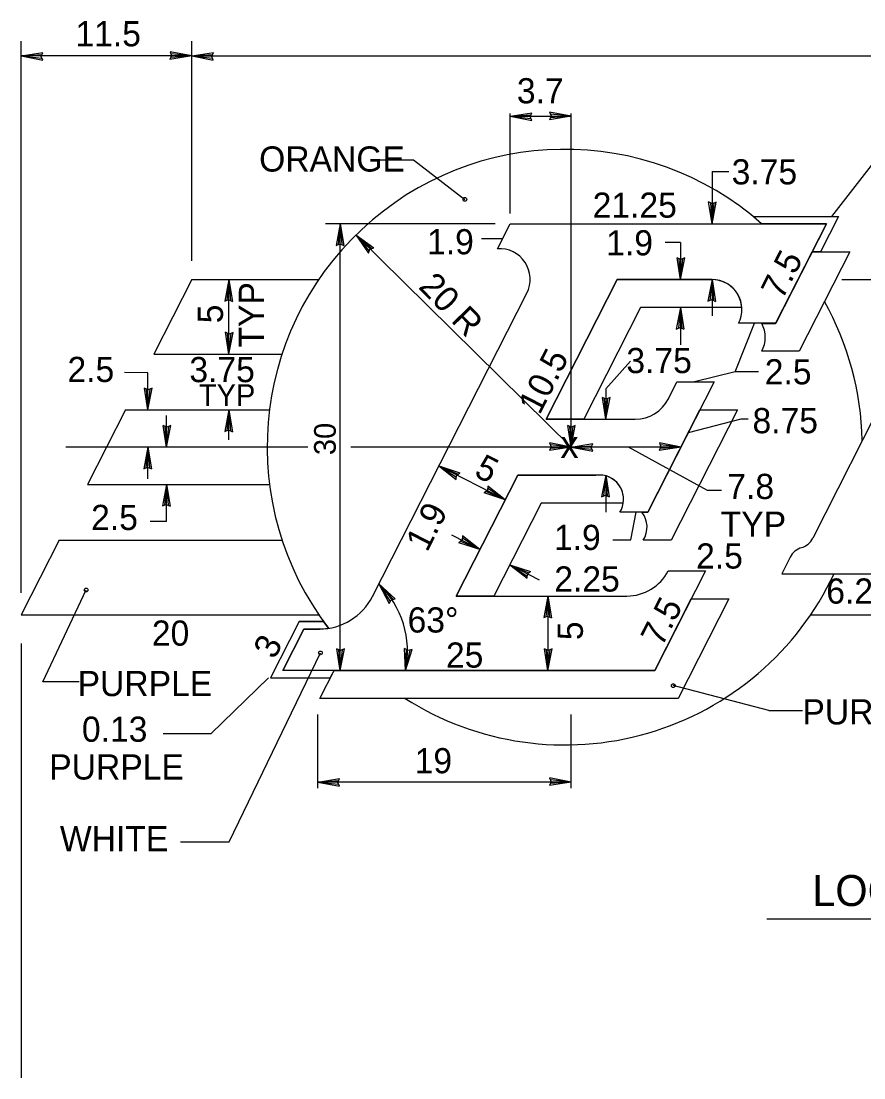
# Model space of a CAD drawing. Extents: x 10268197 to 10268739, y 2141503 to 2142677.
# Drawn here: x 10268676.64 to 10268700.09, y 2142394.92 to 2142424.3 of the extents above; entities that cross this region are included whole.
import ezdxf

# ---------------------------------------------------------------- set-up
doc = ezdxf.new("R2010")
doc.units = 0
for name, color, linetype in [('1', 7, 'Continuous'), ('21', 7, 'Continuous'), ('Default', 7, 'Continuous')]:
    doc.layers.add(name, color=color, linetype=linetype)

msp = doc.modelspace()

# ---------------------------------------------------------------- linework, layer by layer
at = {"layer": '1'}
for p, q in [((10268676.642, 2142408.409), (10268676.642, 2142423.746)), ((10268681.389, 2142417.633), (10268681.389, 2142423.746)), ((10268681.389, 2142423.333), (10268676.642, 2142423.333)), ((10268681.389, 2142423.333), (10268681.994, 2142423.429)), ((10268681.389, 2142423.333), (10268681.968, 2142423.373)), ((10268681.389, 2142423.333), (10268706.542, 2142423.333)), ((10268681.389, 2142423.333), (10268681.99, 2142423.216)), ((10268681.389, 2142423.333), (10268681.967, 2142423.272)), ((10268681.946, 2142423.323), (10268681.994, 2142423.429)), ((10268681.99, 2142423.216), (10268681.946, 2142423.323)), ((10268690.249, 2142421.657), (10268690.855, 2142421.753)), ((10268690.249, 2142418.952), (10268690.249, 2142421.73)), ((10268690.807, 2142421.647), (10268690.855, 2142421.753)), ((10268691.947, 2142412.457), (10268691.947, 2142421.73)), ((10268690.249, 2142421.657), (10268690.829, 2142421.698)), ((10268690.249, 2142421.657), (10268691.947, 2142421.657)), ((10268690.249, 2142421.657), (10268690.851, 2142421.541)), ((10268690.249, 2142421.657), (10268690.828, 2142421.597)), ((10268690.851, 2142421.541), (10268690.807, 2142421.647)), ((10268699.201, 2142418.868), (10268701.226, 2142421.486)), ((10268686.626, 2142420.448), (10268687.563, 2142420.448)), ((10268687.563, 2142420.448), (10268688.991, 2142419.346)), ((10268695.869, 2142420.118), (10268695.869, 2142418.667)), ((10268695.869, 2142420.118), (10268696.338, 2142420.118)), ((10268695.869, 2142418.667), (10268695.773, 2142419.273)), ((10268695.879, 2142419.224), (10268695.773, 2142419.273)), ((10268695.869, 2142418.667), (10268695.829, 2142419.247)), ((10268695.869, 2142418.667), (10268695.986, 2142419.269)), ((10268695.869, 2142418.667), (10268695.93, 2142419.246)), ((10268695.986, 2142419.269), (10268695.879, 2142419.224)), ((10268689.835, 2142418.667), (10268685.11, 2142418.667)), ((10268685.524, 2142418.667), (10268685.407, 2142418.066)), ((10268685.524, 2142418.667), (10268685.463, 2142418.089)), ((10268685.524, 2142406.246), (10268685.524, 2142418.667)), ((10268685.524, 2142418.667), (10268685.619, 2142418.062)), ((10268685.524, 2142418.667), (10268685.564, 2142418.088)), ((10268691.947, 2142412.457), (10268685.959, 2142418.356)), ((10268685.959, 2142418.356), (10268686.457, 2142418)), ((10268685.959, 2142418.356), (10268686.305, 2142417.851)), ((10268685.959, 2142418.356), (10268686.329, 2142417.907)), ((10268685.959, 2142418.356), (10268686.401, 2142417.979)), ((10268690.038, 2142418.253), (10268689.449, 2142418.253)), ((10268685.407, 2142418.066), (10268685.514, 2142418.11)), ((10268685.514, 2142418.11), (10268685.619, 2142418.062)), ((10268686.305, 2142417.851), (10268686.349, 2142417.959)), ((10268686.349, 2142417.959), (10268686.457, 2142418)), ((10268694.99, 2142418.149), (10268694.56, 2142418.149)), ((10268694.99, 2142418.149), (10268694.99, 2142417.115)), ((10268694.99, 2142417.115), (10268694.894, 2142417.72)), ((10268694.999, 2142417.672), (10268694.894, 2142417.72)), ((10268694.99, 2142417.115), (10268694.95, 2142417.695)), ((10268694.99, 2142417.115), (10268695.107, 2142417.716)), ((10268694.99, 2142417.115), (10268695.051, 2142417.693)), ((10268695.107, 2142417.716), (10268694.999, 2142417.672)), ((10268697.636, 2142415.898), (10268698.652, 2142417.891)), ((10268699.698, 2142417.891), (10268698.287, 2142415.124)), ((10268698.652, 2142417.891), (10268699.698, 2142417.891)), ((10268682.424, 2142417.115), (10268682.307, 2142416.513)), ((10268682.424, 2142417.115), (10268682.363, 2142416.536)), ((10268682.424, 2142415.044), (10268682.424, 2142417.115)), ((10268682.424, 2142417.115), (10268682.52, 2142416.509)), ((10268682.424, 2142417.115), (10268682.464, 2142416.535)), ((10268691.253, 2142413.233), (10268693.231, 2142417.115)), ((10268693.231, 2142417.115), (10268695.869, 2142417.115)), ((10268695.869, 2142417.115), (10268695.752, 2142416.513)), ((10268695.869, 2142417.115), (10268695.808, 2142416.536)), ((10268695.869, 2142417.115), (10268695.965, 2142416.509)), ((10268695.869, 2142417.115), (10268695.91, 2142416.535)), ((10268695.869, 2142417.115), (10268695.869, 2142416.104)), ((10268682.307, 2142416.513), (10268682.414, 2142416.557)), ((10268682.414, 2142416.557), (10268682.52, 2142416.509)), ((10268695.752, 2142416.513), (10268695.859, 2142416.557)), ((10268695.859, 2142416.557), (10268695.965, 2142416.509)), ((10268693.881, 2142416.339), (10268692.299, 2142413.233)), ((10268696.696, 2142416.339), (10268693.881, 2142416.339)), ((10268694.99, 2142416.339), (10268694.873, 2142415.737)), ((10268694.99, 2142416.339), (10268694.93, 2142415.76)), ((10268694.99, 2142416.339), (10268694.99, 2142415.304)), ((10268694.99, 2142416.339), (10268695.086, 2142415.733)), ((10268694.99, 2142416.339), (10268695.031, 2142415.759)), ((10268696.515, 2142414.546), (10268697.046, 2142415.9)), ((10268697.251, 2142415.898), (10268697.636, 2142415.898)), ((10268682.424, 2142415.044), (10268682.328, 2142415.65)), ((10268682.433, 2142415.602), (10268682.328, 2142415.65)), ((10268682.424, 2142415.044), (10268682.382, 2142415.624)), ((10268682.424, 2142415.044), (10268682.541, 2142415.646)), ((10268682.424, 2142415.044), (10268682.484, 2142415.623)), ((10268682.541, 2142415.646), (10268682.433, 2142415.602)), ((10268694.873, 2142415.737), (10268694.981, 2142415.781)), ((10268694.981, 2142415.781), (10268695.086, 2142415.733)), ((10268698.287, 2142415.124), (10268697.252, 2142415.124)), ((10268693.594, 2142414.845), (10268692.912, 2142414.075)), ((10268680.172, 2142414.527), (10268679.516, 2142414.531)), ((10268680.172, 2142413.492), (10268680.172, 2142414.527)), ((10268696.515, 2142414.546), (10268695.375, 2142414.268)), ((10268697.157, 2142414.546), (10268696.515, 2142414.546)), ((10268680.172, 2142413.492), (10268680.076, 2142414.097)), ((10268680.181, 2142414.049), (10268680.076, 2142414.097)), ((10268680.172, 2142413.492), (10268680.288, 2142414.093)), ((10268680.288, 2142414.093), (10268680.181, 2142414.049)), ((10268680.172, 2142413.492), (10268680.131, 2142414.072)), ((10268680.172, 2142413.492), (10268680.232, 2142414.07)), ((10268692.912, 2142413.233), (10268692.816, 2142413.838)), ((10268692.921, 2142413.79), (10268692.816, 2142413.838)), ((10268692.912, 2142413.233), (10268692.871, 2142413.813)), ((10268692.912, 2142414.075), (10268692.912, 2142413.233)), ((10268692.912, 2142413.233), (10268693.028, 2142413.835)), ((10268692.912, 2142413.233), (10268692.972, 2142413.811)), ((10268693.028, 2142413.835), (10268692.921, 2142413.79)), ((10268680.69, 2142412.457), (10268680.69, 2142413.336)), ((10268682.424, 2142413.492), (10268682.307, 2142412.89)), ((10268682.424, 2142413.492), (10268682.363, 2142412.914)), ((10268682.424, 2142412.664), (10268682.424, 2142413.492)), ((10268682.424, 2142413.492), (10268682.52, 2142412.886)), ((10268682.424, 2142413.492), (10268682.464, 2142412.912)), ((10268692.299, 2142413.233), (10268691.253, 2142413.233)), ((10268694.08, 2142410.645), (10268695.531, 2142413.492)), ((10268696.576, 2142413.492), (10268694.73, 2142409.869)), ((10268696.669, 2142413.234), (10268695.206, 2142412.854)), ((10268695.531, 2142413.492), (10268696.576, 2142413.492)), ((10268696.875, 2142413.234), (10268696.669, 2142413.234)), ((10268680.69, 2142412.457), (10268680.593, 2142413.062)), ((10268680.699, 2142413.014), (10268680.593, 2142413.062)), ((10268680.69, 2142412.457), (10268680.649, 2142413.036)), ((10268680.69, 2142412.457), (10268680.806, 2142413.058)), ((10268680.69, 2142412.457), (10268680.75, 2142413.035)), ((10268680.806, 2142413.058), (10268680.699, 2142413.014)), ((10268682.307, 2142412.89), (10268682.414, 2142412.935)), ((10268682.414, 2142412.935), (10268682.52, 2142412.886)), ((10268691.947, 2142412.457), (10268691.851, 2142413.062)), ((10268691.956, 2142413.014), (10268691.851, 2142413.062)), ((10268691.947, 2142412.457), (10268691.906, 2142413.036)), ((10268691.947, 2142412.457), (10268692.063, 2142413.058)), ((10268691.947, 2142412.457), (10268692.007, 2142413.035)), ((10268692.063, 2142413.058), (10268691.956, 2142413.014)), ((10268684.62, 2142412.457), (10268677.886, 2142412.457)), ((10268680.172, 2142412.457), (10268680.055, 2142411.855)), ((10268680.172, 2142412.457), (10268680.111, 2142411.878)), ((10268680.172, 2142411.577), (10268680.172, 2142412.457)), ((10268680.172, 2142412.457), (10268680.268, 2142411.851)), ((10268680.172, 2142412.457), (10268680.213, 2142411.877)), ((10268691.947, 2142412.457), (10268685.814, 2142412.457)), ((10268691.389, 2142412.467), (10268691.341, 2142412.361)), ((10268691.947, 2142412.457), (10268691.341, 2142412.361)), ((10268691.947, 2142412.457), (10268691.345, 2142412.574)), ((10268691.345, 2142412.574), (10268691.389, 2142412.467)), ((10268691.947, 2142412.457), (10268691.367, 2142412.416)), ((10268691.947, 2142412.457), (10268691.369, 2142412.517)), ((10268691.947, 2142412.457), (10268692.552, 2142412.553)), ((10268691.947, 2142412.457), (10268692.526, 2142412.497)), ((10268695.004, 2142412.457), (10268691.947, 2142412.457)), ((10268691.947, 2142412.457), (10268692.548, 2142412.34)), ((10268691.947, 2142412.457), (10268692.525, 2142412.396)), ((10268692.504, 2142412.447), (10268692.552, 2142412.553)), ((10268692.548, 2142412.34), (10268692.504, 2142412.447)), ((10268695.743, 2142411.252), (10268693.54, 2142412.457)), ((10268694.446, 2142412.467), (10268694.398, 2142412.361)), ((10268695.004, 2142412.457), (10268694.398, 2142412.361)), ((10268695.004, 2142412.457), (10268694.402, 2142412.574)), ((10268694.402, 2142412.574), (10268694.446, 2142412.467)), ((10268695.004, 2142412.457), (10268694.424, 2142412.416)), ((10268695.004, 2142412.457), (10268694.425, 2142412.517)), ((10268680.055, 2142411.855), (10268680.162, 2142411.9)), ((10268680.162, 2142411.9), (10268680.268, 2142411.851)), ((10268690.113, 2142410.993), (10268688.267, 2142411.933)), ((10268688.267, 2142411.933), (10268688.85, 2142411.744)), ((10268688.267, 2142411.933), (10268688.751, 2142411.556)), ((10268688.267, 2142411.933), (10268688.755, 2142411.617)), ((10268688.267, 2142411.933), (10268688.802, 2142411.706)), ((10268688.76, 2142411.671), (10268688.85, 2142411.744)), ((10268688.749, 2142408.317), (10268690.463, 2142411.68)), ((10268688.751, 2142411.556), (10268688.76, 2142411.671)), ((10268690.463, 2142411.68), (10268692.636, 2142411.673)), ((10268692.912, 2142411.68), (10268692.795, 2142411.079)), ((10268692.912, 2142411.68), (10268692.851, 2142411.102)), ((10268692.912, 2142411.68), (10268693.008, 2142411.075)), ((10268692.912, 2142411.68), (10268692.952, 2142411.101)), ((10268692.912, 2142411.68), (10268692.912, 2142410.645)), ((10268680.69, 2142411.422), (10268680.573, 2142410.82)), ((10268680.69, 2142411.422), (10268680.629, 2142410.843)), ((10268680.69, 2142410.387), (10268680.69, 2142411.422)), ((10268680.69, 2142411.422), (10268680.786, 2142410.816)), ((10268680.69, 2142411.422), (10268680.73, 2142410.842)), ((10268689.62, 2142411.254), (10268689.529, 2142411.182)), ((10268690.113, 2142410.993), (10268689.529, 2142411.182)), ((10268690.113, 2142410.993), (10268689.577, 2142411.219)), ((10268689.629, 2142411.37), (10268689.62, 2142411.254)), ((10268690.113, 2142410.993), (10268689.625, 2142411.309)), ((10268690.113, 2142410.993), (10268689.629, 2142411.37)), ((10268696.129, 2142411.252), (10268695.743, 2142411.252)), ((10268680.573, 2142410.82), (10268680.68, 2142410.865)), ((10268680.68, 2142410.865), (10268680.786, 2142410.816)), ((10268691.112, 2142410.903), (10268689.794, 2142408.317)), ((10268693.397, 2142410.895), (10268691.112, 2142410.903)), ((10268692.795, 2142411.079), (10268692.902, 2142411.123)), ((10268692.902, 2142411.123), (10268693.008, 2142411.075)), ((10268693.603, 2142409.882), (10268693.759, 2142410.645)), ((10268693.918, 2142410.645), (10268694.08, 2142410.645)), ((10268680.69, 2142410.387), (10268680.231, 2142410.391)), ((10268689.408, 2142409.61), (10268688.626, 2142410.008)), ((10268688.925, 2142409.987), (10268688.915, 2142409.872)), ((10268689.408, 2142409.61), (10268688.925, 2142409.987)), ((10268688.915, 2142409.872), (10268688.825, 2142409.799)), ((10268689.408, 2142409.61), (10268688.825, 2142409.799)), ((10268689.408, 2142409.61), (10268688.873, 2142409.837)), ((10268689.408, 2142409.61), (10268688.92, 2142409.926)), ((10268693.108, 2142409.882), (10268693.603, 2142409.882)), ((10268694.73, 2142409.869), (10268693.954, 2142409.869)), ((10268691.07, 2142408.762), (10268690.237, 2142409.186)), ((10268690.237, 2142409.186), (10268690.82, 2142408.997)), ((10268690.237, 2142409.186), (10268690.72, 2142408.809)), ((10268690.237, 2142409.186), (10268690.725, 2142408.87)), ((10268690.237, 2142409.186), (10268690.772, 2142408.96)), ((10268690.72, 2142408.809), (10268690.73, 2142408.925)), ((10268690.73, 2142408.925), (10268690.82, 2142408.997)), ((10268686.595, 2142408.651), (10268687.052, 2142408.242)), ((10268686.595, 2142408.651), (10268686.885, 2142408.111)), ((10268686.595, 2142408.651), (10268686.914, 2142408.164)), ((10268686.595, 2142408.651), (10268686.994, 2142408.227)), ((10268677.248, 2142405.934), (10268678.453, 2142408.484)), ((10268686.885, 2142408.111), (10268686.94, 2142408.213)), ((10268686.94, 2142408.213), (10268687.052, 2142408.242)), ((10268689.794, 2142408.317), (10268688.749, 2142408.317)), ((10268691.301, 2142408.317), (10268691.184, 2142407.715)), ((10268691.301, 2142408.317), (10268691.24, 2142407.738)), ((10268691.301, 2142408.317), (10268691.301, 2142406.246)), ((10268691.301, 2142408.317), (10268691.397, 2142407.711)), ((10268691.301, 2142408.317), (10268691.341, 2142407.737)), ((10268694.272, 2142406.246), (10268695.286, 2142408.237)), ((10268696.332, 2142408.237), (10268694.922, 2142405.469)), ((10268695.286, 2142408.237), (10268696.332, 2142408.237)), ((10268691.184, 2142407.715), (10268691.292, 2142407.759)), ((10268691.292, 2142407.759), (10268691.397, 2142407.711)), ((10268676.642, 2142406.997), (10268676.642, 2142394.918)), ((10268685.524, 2142406.246), (10268685.428, 2142406.851)), ((10268685.533, 2142406.803), (10268685.428, 2142406.851)), ((10268685.524, 2142406.246), (10268685.483, 2142406.826)), ((10268685.524, 2142406.246), (10268685.641, 2142406.847)), ((10268685.524, 2142406.246), (10268685.584, 2142406.824)), ((10268685.641, 2142406.847), (10268685.533, 2142406.803)), ((10268687.336, 2142406.246), (10268687.314, 2142406.859)), ((10268687.413, 2142406.798), (10268687.314, 2142406.859)), ((10268687.336, 2142406.246), (10268687.525, 2142406.829)), ((10268687.336, 2142406.246), (10268687.366, 2142406.827)), ((10268687.336, 2142406.246), (10268687.466, 2142406.813)), ((10268687.525, 2142406.829), (10268687.413, 2142406.798)), ((10268691.301, 2142406.246), (10268691.205, 2142406.851)), ((10268691.311, 2142406.803), (10268691.205, 2142406.851)), ((10268691.301, 2142406.246), (10268691.26, 2142406.826)), ((10268691.301, 2142406.246), (10268691.417, 2142406.847)), ((10268691.301, 2142406.246), (10268691.361, 2142406.824)), ((10268691.417, 2142406.847), (10268691.311, 2142406.803)), ((10268682.434, 2142401.477), (10268684.97, 2142406.735)), ((10268684.956, 2142405.469), (10268685.352, 2142406.246)), ((10268685.352, 2142406.246), (10268694.272, 2142406.246)), ((10268678.256, 2142405.934), (10268677.248, 2142405.934)), ((10268681.932, 2142404.492), (10268683.527, 2142406.039)), ((10268697.447, 2142405.129), (10268694.789, 2142405.824)), ((10268694.922, 2142405.469), (10268684.956, 2142405.469)), ((10268684.896, 2142402.97), (10268684.896, 2142405.026)), ((10268691.947, 2142402.97), (10268691.947, 2142405.026)), ((10268697.447, 2142405.129), (10268698.384, 2142405.129)), ((10268680.595, 2142404.492), (10268681.932, 2142404.492)), ((10268691.947, 2142403.145), (10268684.896, 2142403.145)), ((10268681.078, 2142401.486), (10268682.434, 2142401.486))]:
    msp.add_line(p, q, dxfattribs=at)
msp.add_lwpolyline([(10268697.01, 2142418.868), (10268699.382, 2142418.868), (10268698.885, 2142417.891), (10268698.652, 2142417.891), (10268699.048, 2142418.667), (10268697.246, 2142418.667)], close=True, dxfattribs=at)
for centre in [(10268688.991, 2142419.346), (10268678.453, 2142408.484), (10268684.97, 2142406.735), (10268694.789, 2142405.824)]:
    msp.add_circle(centre, 0.0518, dxfattribs=at)
for centre, radius, start, end in [((10268695.869, 2142416.287), 0.828, 3.5833, 90), ((10268696.519, 2142415.51), 0.828, 332.2089, 27.9127), ((10268692.734, 2142411.008), 0.673, 350.3502, 98.3344), ((10268693.387, 2142410.232), 0.673, 327.421, 37.9799), ((10268684.804, 2142406.783), 2.588, 348.03, 46.2026)]:
    msp.add_arc(centre, radius, start, end, dxfattribs=at)
at = {"layer": '21'}
for p, q in [((10268676.642, 2142423.333), (10268677.247, 2142423.429)), ((10268676.642, 2142423.333), (10268677.222, 2142423.373)), ((10268676.642, 2142423.333), (10268677.244, 2142423.216)), ((10268676.642, 2142423.333), (10268677.22, 2142423.272)), ((10268677.2, 2142423.323), (10268677.247, 2142423.429)), ((10268677.244, 2142423.216), (10268677.2, 2142423.323)), ((10268680.831, 2142423.343), (10268680.783, 2142423.236)), ((10268681.389, 2142423.333), (10268680.783, 2142423.236)), ((10268681.389, 2142423.333), (10268680.787, 2142423.449)), ((10268680.787, 2142423.449), (10268680.831, 2142423.343)), ((10268681.389, 2142423.333), (10268680.809, 2142423.292)), ((10268681.389, 2142423.333), (10268680.81, 2142423.393)), ((10268691.947, 2142421.657), (10268691.345, 2142421.774)), ((10268691.345, 2142421.774), (10268691.389, 2142421.666)), ((10268691.389, 2142421.666), (10268691.341, 2142421.561)), ((10268691.947, 2142421.657), (10268691.341, 2142421.561)), ((10268691.947, 2142421.657), (10268691.367, 2142421.617)), ((10268691.947, 2142421.657), (10268691.369, 2142421.718)), ((10268684.896, 2142403.145), (10268685.502, 2142403.241)), ((10268685.454, 2142403.135), (10268685.502, 2142403.241)), ((10268691.947, 2142403.145), (10268691.345, 2142403.261)), ((10268691.345, 2142403.261), (10268691.389, 2142403.154)), ((10268684.896, 2142403.145), (10268685.476, 2142403.185)), ((10268684.896, 2142403.145), (10268685.498, 2142403.028)), ((10268684.896, 2142403.145), (10268685.475, 2142403.084)), ((10268685.498, 2142403.028), (10268685.454, 2142403.135)), ((10268691.389, 2142403.154), (10268691.342, 2142403.048)), ((10268691.947, 2142403.145), (10268691.342, 2142403.048)), ((10268691.947, 2142403.145), (10268691.367, 2142403.104)), ((10268691.947, 2142403.145), (10268691.369, 2142403.205)), ((10268697.392, 2142399.342), (10268708.293, 2142399.342))]:
    msp.add_line(p, q, dxfattribs=at)
at = {"layer": 'Default'}
for p, q in [((10268697.01, 2142418.868), (10268699.382, 2142418.868)), ((10268699.382, 2142418.868), (10268698.885, 2142417.891)), ((10268689.896, 2142417.973), (10268690.249, 2142418.667)), ((10268690.249, 2142418.667), (10268699.048, 2142418.667)), ((10268699.048, 2142418.667), (10268697.638, 2142415.9)), ((10268697.636, 2142415.898), (10268698.652, 2142417.891)), ((10268699.698, 2142417.891), (10268698.287, 2142415.124)), ((10268698.652, 2142417.891), (10268699.698, 2142417.891)), ((10268681.389, 2142417.115), (10268680.334, 2142415.044)), ((10268681.389, 2142417.115), (10268684.922, 2142417.115)), ((10268693.231, 2142417.115), (10268691.253, 2142413.233)), ((10268691.253, 2142413.233), (10268693.231, 2142417.115)), ((10268695.869, 2142417.115), (10268693.231, 2142417.115)), ((10268693.231, 2142417.115), (10268695.869, 2142417.115)), ((10268699.479, 2142417.115), (10268729.003, 2142417.115)), ((10268686.418, 2142408.303), (10268690.713, 2142416.734)), ((10268693.881, 2142416.339), (10268692.299, 2142413.233)), ((10268696.696, 2142416.339), (10268693.881, 2142416.339)), ((10268697.638, 2142415.9), (10268696.602, 2142415.9)), ((10268697.251, 2142415.898), (10268697.636, 2142415.898)), ((10268680.334, 2142415.044), (10268683.903, 2142415.044)), ((10268698.287, 2142415.124), (10268697.252, 2142415.124)), ((10268701.234, 2142414.991), (10268698.672, 2142409.923)), ((10268695.926, 2142414.268), (10268694.08, 2142410.645)), ((10268694.651, 2142413.798), (10268694.891, 2142414.268)), ((10268694.891, 2142414.268), (10268695.926, 2142414.268)), ((10268679.543, 2142413.492), (10268678.488, 2142411.422)), ((10268679.543, 2142413.492), (10268683.553, 2142413.492)), ((10268691.253, 2142413.233), (10268693.73, 2142413.233)), ((10268692.299, 2142413.233), (10268691.253, 2142413.233)), ((10268694.08, 2142410.645), (10268695.531, 2142413.492)), ((10268696.576, 2142413.492), (10268694.73, 2142409.869)), ((10268695.531, 2142413.492), (10268696.576, 2142413.492)), ((10268690.463, 2142411.68), (10268688.749, 2142408.317)), ((10268688.749, 2142408.317), (10268690.463, 2142411.68)), ((10268692.734, 2142411.68), (10268690.463, 2142411.68)), ((10268690.463, 2142411.68), (10268692.636, 2142411.673)), ((10268678.488, 2142411.422), (10268683.553, 2142411.422)), ((10268691.112, 2142410.903), (10268689.794, 2142408.317)), ((10268693.397, 2142410.895), (10268691.112, 2142410.903)), ((10268694.08, 2142410.645), (10268693.301, 2142410.645)), ((10268693.918, 2142410.645), (10268694.08, 2142410.645)), ((10268677.697, 2142409.869), (10268676.642, 2142407.798)), ((10268677.697, 2142409.869), (10268683.903, 2142409.869)), ((10268694.73, 2142409.869), (10268693.954, 2142409.869)), ((10268698.042, 2142409.397), (10268697.81, 2142408.937)), ((10268695.682, 2142409.013), (10268694.272, 2142406.246)), ((10268694.646, 2142409.013), (10268695.682, 2142409.013)), ((10268697.81, 2142408.937), (10268700.397, 2142408.937)), ((10268688.749, 2142408.317), (10268693.498, 2142408.317)), ((10268689.794, 2142408.317), (10268688.749, 2142408.317)), ((10268694.272, 2142406.246), (10268695.286, 2142408.237)), ((10268696.332, 2142408.237), (10268694.922, 2142405.469)), ((10268695.286, 2142408.237), (10268696.332, 2142408.237)), ((10268676.642, 2142407.798), (10268684.922, 2142407.798)), ((10268698.615, 2142407.798), (10268724.257, 2142407.798)), ((10268684.381, 2142407.607), (10268683.583, 2142406.039)), ((10268683.921, 2142406.246), (10268684.508, 2142407.399)), ((10268684.508, 2142407.399), (10268683.922, 2142406.246)), ((10268684.381, 2142407.607), (10268685.057, 2142407.607)), ((10268684.943, 2142407.4), (10268684.508, 2142407.399)), ((10268684.508, 2142407.399), (10268684.943, 2142407.399)), ((10268694.272, 2142406.246), (10268683.921, 2142406.246)), ((10268684.956, 2142405.469), (10268685.352, 2142406.246)), ((10268685.352, 2142406.246), (10268694.272, 2142406.246)), ((10268683.583, 2142406.039), (10268685.246, 2142406.039)), ((10268694.922, 2142405.469), (10268684.956, 2142405.469))]:
    msp.add_line(p, q, dxfattribs=at)
msp.add_lwpolyline([(10268685.057, 2142407.607), (10268684.381, 2142407.607), (10268683.583, 2142406.039), (10268685.246, 2142406.039), (10268685.352, 2142406.246), (10268683.921, 2142406.246), (10268684.508, 2142407.399), (10268684.943, 2142407.399), (10268685.197, 2142407.419)], close=True, dxfattribs=at)
for centre, radius, start, end in [((10268691.769, 2142412.457), 8.281, 48.5904, 217.4725), ((10268689.953, 2142417.122), 0.854, 332.9998, 93.8045), ((10268695.869, 2142416.287), 0.828, 332.2089, 90), ((10268695.869, 2142416.287), 0.828, 3.5833, 90), ((10268691.769, 2142412.457), 8.281, 1.2967, 29.2778), ((10268696.519, 2142415.51), 0.828, 332.2089, 27.9127), ((10268693.729, 2142414.268), 1.035, 270, 332.9883), ((10268692.734, 2142411.008), 0.673, 350.3502, 98.3344), ((10268692.734, 2142411.008), 0.673, 327.421, 90), ((10268693.387, 2142410.232), 0.673, 327.421, 37.9799), ((10268691.769, 2142412.457), 8.281, 237.5383, 334.8493), ((10268693.498, 2142409.61), 1.294, 270, 332.5096), ((10268684.943, 2142409.056), 1.656, 270, 332.9991)]:
    msp.add_arc(centre, radius, start, end, dxfattribs=at)
for centre, start_param, end_param in [((10268698.211, 2142410.161), 0.286787, 1.099486), ((10268698.504, 2142409.161), 3.428379, 4.240701)]:
    msp.add_ellipse(centre, major_axis=(0, -0.521), ratio=0.992614, start_param=start_param, end_param=end_param, dxfattribs=at)

# ---------------------------------------------------------------- texts
at = {"layer": '1'}
for s, height, p in [('11.5', 0.7, (10268678.154, 2142423.602)), ('3.7', 0.7, (10268690.436, 2142422.016)), ('ORANGE', 0.7, (10268683.265, 2142420.119)), ('3.75', 0.7, (10268696.413, 2142419.762)), ('21.25', 0.7, (10268692.545, 2142418.835)), ('1.9', 0.7, (10268687.938, 2142417.818)), ('1.9', 0.7, (10268692.922, 2142417.788)), ('2.5', 0.7, (10268677.932, 2142414.267)), ('3.75', 0.7, (10268681.324, 2142414.263)), ('3.75', 0.7, (10268693.483, 2142414.514)), ('2.5', 0.7, (10268697.334, 2142414.202)), ('TYP', 0.6037, (10268681.589, 2142413.602)), ('8.75', 0.7, (10268696.993, 2142412.843)), ('x', 0.755, (10268691.648, 2142412.156)), ('7.8', 0.7, (10268696.293, 2142411.014)), ('2.5', 0.7, (10268678.59, 2142410.152)), ('TYP', 0.7, (10268696.108, 2142409.964)), ('1.9', 0.7, (10268691.469, 2142409.597)), ('2.5', 0.7, (10268695.424, 2142409.08)), ('2.25', 0.7, (10268691.478, 2142408.44)), ('6.25', 0.7, (10268699.046, 2142408.105)), ('63°', 0.7, (10268687.396, 2142407.301)), ('20', 0.7, (10268680.28, 2142406.936)), ('25', 0.7, (10268688.463, 2142406.325)), ('PURPLE', 0.7, (10268678.214, 2142405.533)), ('PURPLE', 0.7, (10268698.382, 2142404.746)), ('0.13', 0.7, (10268678.334, 2142404.264)), ('PURPLE', 0.7, (10268677.425, 2142403.214)), ('19', 0.7, (10268687.593, 2142403.388)), ('WHITE', 0.7, (10268677.722, 2142401.219)), ('LOGO EP-20R', 0.8624, (10268698.657, 2142399.696))]:
    msp.add_text(s, height=height, dxfattribs=at).set_placement(p)
for s, height, rotation, p in [('7.5', 0.7, 63, (10268697.82, 2142416.53)), ('20 R', 0.7, 314.1812, (10268687.673, 2142416.895)), ('TYP', 0.7, 90, (10268683.399, 2142415.225)), ('5', 0.7, 90, (10268682.258, 2142415.9)), ('10.5', 0.7, 63.0402, (10268691.069, 2142413.329)), ('30', 0.6037, 90, (10268685.397, 2142412.235)), ('5', 0.7, 332.9866, (10268689.216, 2142411.666)), ('1.9', 0.7, 63.0402, (10268687.939, 2142409.516)), ('7.5', 0.7, 63, (10268694.474, 2142406.88)), ('5', 0.7, 90, (10268692.273, 2142407.089)), ('3', 0.7, 63, (10268683.697, 2142406.532))]:
    msp.add_text(s, height=height, rotation=rotation, dxfattribs=at).set_placement(p)

doc.saveas('drawing.dxf')
